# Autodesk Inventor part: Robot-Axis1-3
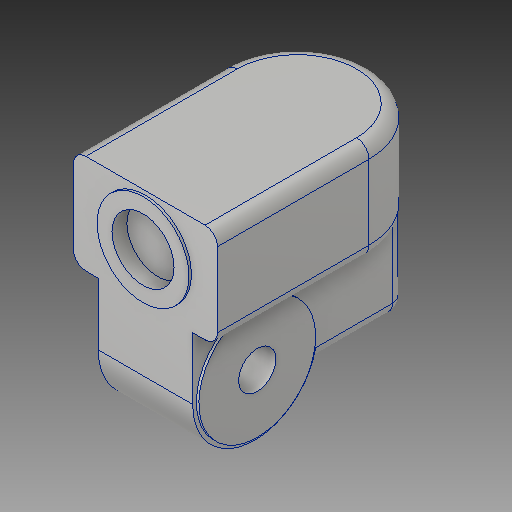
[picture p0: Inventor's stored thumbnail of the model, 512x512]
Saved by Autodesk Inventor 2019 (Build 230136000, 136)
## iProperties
Created: 2018-07
Part Number: Robot-Axis1-3
Material: Aluminum 6061
Description: 123456
Document SubType Name: Modeling
Designer: Power User
Mass: 6944.94 g
Surface Area: 1273.07 cm^2
Volume: 2572.2 cm^3
Density: 2.7 g/cm^3
Appearance: Aluminum - Flat
Title: GEAR
Author: Power User
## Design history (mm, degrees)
sketch "Sketch6" dims "d50" = 100
  geometry: L1 (-58, 150)-(58, 150); L2 (58, 150)-(58, 70); L3 (58, 70)-(-58, 70); L4 (-58, 70)-(-58, 150); L5 (-58, 150)-(58, 70); L6 (58, 150)-(-58, 70); L7 (-38, 20)-(38, 20); L8 (38, 20)-(38, 70); L9 (38, 70)-(-38, 70); L10 (-38, 70)-(-38, 20); L11 (-38, 20)-(38, 70); L12 (38, 20)-(-38, 70); 8 further points
  constraints: 24 end point, 8 midpoint, 3 parallel, 2 perpendicular, 2 vertical alignment, 1 coincident, 1 collinear, 1 horizontal
  dimensions: "d44" = 116 distance of L2.end L3.end; "d45" = 80 distance of L1.end L2.end; "d47" = 76 distance of L7.start L7.end; "d54" = 130 distance between parallel lines of L1 L7; "d55" = 150 distance from line of L1 point (0, 0)
extrude "Extrusion5" new body sketch "Sketch6" distance "d48" = 180; taper "d49" = 0 deg
sketch "Sketch7"
  geometry: L1 (20, -180)-(20, 0) reference; L2 (20, 0)-(150, 0) reference; L3 (150, 0)-(150, -180) reference; L4 (150, -180)-(20, -180) reference; C1 r 50 at (20, -50); C2 r 47 at (20, -50)
  constraints: 2 centre point, 1 coincident, 1 tangent
  dimensions: "d50" = 100 diameter of C1; "d51" = 130 distance from line of C1.centre L3; "d74" = 94 diameter of C2
  node "Project Cut Edges2"
extrude "Extrusion6" join sketch "Sketch7" stored distance "d52" = 76; taper "d53" = 0 deg
extrude "Extrusion9" join sketch "Sketch7" stored distance "d75" = 80; taper "d76" = 0 deg
sketch "Sketch11"
  geometry: C1 r 47 at (0, 0) reference; 2 further points
  constraints: 1 coincident
hole "Hole3" sketch "Sketch11" at (0, 0) diameter "d78" = 30; stored, may be unused: countersink angle "d82" = 90 deg, drill point angle "d84" = 118 deg; dims "d79" = 6, "d80" = 4, "d81" = 2, "d83" = 8
node "Direct Edit1"
sketch "Sketch8"
  geometry: L1 (58, 150)-(58, 70) reference; C1 r 25 at (0, 110); C2 r 37 at (0, 110); 2 further points
  constraints: 2 centre point, 1 coincident, 1 horizontal alignment, 1 midpoint, 1 vertical alignment
  dimensions: "d59" = 50 diameter of C1; "d60" = 74 diameter of C2
extrude "Extrusion7" join sketch "Sketch8" distance "d62" = 2; taper "d63" = 0 deg
sketch "Sketch9"
  geometry: C1 r 25 at (0, 0) reference; 1 further point
extrude "Extrusion8" cut sketch "Sketch9" distance "d64" = 10; taper "d65" = 0 deg
fillet "Fillet2"
fillet "Fillet3" dims "d73" = 10
body "Solid2"
node "Projected Loop1"
move_body "Move1" dims "d58" = 20
other parameters: "d56" = 0, "d57" = 0
